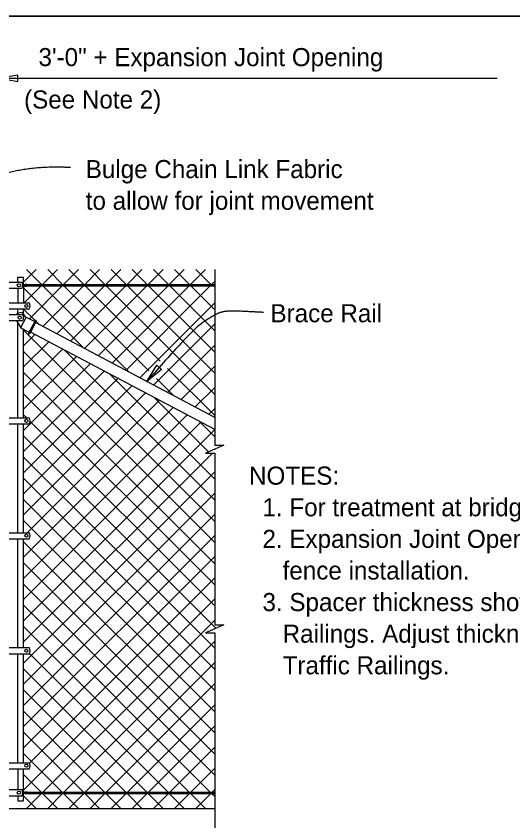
# Model space of a CAD drawing. Extents: x 0 to 41.2, y 0 to 26.
# Drawn here: x 28.76 to 34.3, y 17 to 25.96 of the extents above; entities that cross this region are included whole.
import ezdxf

# ---------------------------------------------------------------- set-up
doc = ezdxf.new("R2010")
doc.units = 0
for name, color, linetype in [('ActivePts-ConstElements', 7, 'Continuous'), ('Dimension', 7, 'Continuous'), ('Miscellaneous', 7, 'Continuous'), ('Miscellaneous1', 7, 'Continuous'), ('SteelMisc', 7, 'Continuous'), ('SupstrConc', 7, 'Continuous'), ('TextStructures', 7, 'Continuous')]:
    doc.layers.add(name, color=color, linetype=linetype)

msp = doc.modelspace()

# ---------------------------------------------------------------- linework, layer by layer
at = {"layer": 'ActivePts-ConstElements'}
msp.add_lwpolyline([(0, 0), (41.2106, 0), (41.2106, 25.96), (0, 25.96)], close=True, dxfattribs=at)
at = {"layer": 'Dimension'}
msp.add_line((25.6609, 25.2672), (34.1233, 25.2672), dxfattribs=at)
for points in [[(28.5762, 25.2672), (28.7845, 25.2319), (28.7845, 25.3025)], [(30.3825, 22.0243), (30.2184, 21.8914), (30.3296, 22.071)]]:
    msp.add_lwpolyline(points, close=True, dxfattribs=at)
for points in [[(30.9762, 23.1382), (30.9762, 21.1819), (31.0795, 21.1819), (30.9762, 21.1369), (30.8729, 21.0919), (30.9762, 21.0919), (30.9762, 20.1983)], [(30.9762, 20.1983), (30.9762, 19.1806), (31.0795, 19.1806), (30.9762, 19.1356), (30.8729, 19.0906), (30.9762, 19.0906), (30.9762, 17.1361)], [(30.9761, 17.1361), (30.9761, 15.7022), (31.0795, 15.7022), (30.9761, 15.6572), (30.8728, 15.6122), (30.9761, 15.6122), (30.9761, 13.3448)]]:
    msp.add_lwpolyline(points, dxfattribs=at)
for points in [[(29.3712, 24.2725), (28.9427, 24.2977), (28.2117, 24.0791), (27.9092, 23.4903), (27.7412, 21.9834)], [(31.5199, 22.6596), (31.3633, 22.6678), (31.0749, 22.6809), (30.9256, 22.6043), (30.718, 22.4586), (30.2184, 21.8914)]]:
    msp.add_open_spline(points, degree=2, dxfattribs=at)
at = {"layer": 'Miscellaneous'}
for p, q in [((28.8471, 22.996), (28.9872, 23.1361)), ((28.8798, 23.1361), (29.0465, 22.9695)), ((29.0563, 22.9695), (29.2229, 23.1361)), ((29.1155, 23.1361), (29.2822, 22.9695)), ((29.292, 22.9695), (29.4586, 23.1361)), ((29.3512, 23.1361), (29.5179, 22.9695)), ((29.5277, 22.9695), (29.6943, 23.1361)), ((29.5869, 23.1361), (29.7536, 22.9695)), ((29.7634, 22.9695), (29.9301, 23.1361)), ((29.8226, 23.1361), (29.9893, 22.9695)), ((29.9991, 22.9695), (30.1658, 23.1361)), ((30.0583, 23.1361), (30.225, 22.9695)), ((30.2348, 22.9695), (30.4015, 23.1361)), ((30.294, 23.1361), (30.4607, 22.9695)), ((30.4705, 22.9695), (30.6372, 23.1361)), ((30.5297, 23.1361), (30.6964, 22.9695)), ((30.7062, 22.9695), (30.8729, 23.1361)), ((30.7654, 23.1361), (30.9321, 22.9695)), ((28.8522, 22.7654), (29.0415, 22.9547)), ((28.912, 22.5894), (29.2772, 22.9547)), ((29.0612, 22.9547), (30.0194, 21.9966)), ((29.0612, 22.5029), (29.5129, 22.9547)), ((29.2154, 22.4214), (29.7486, 22.9547)), ((29.2969, 22.9547), (30.2432, 22.0084)), ((29.3696, 22.3399), (29.9843, 22.9547)), ((29.5238, 22.2584), (30.22, 22.9547)), ((29.5326, 22.9547), (30.3688, 22.1185)), ((29.678, 22.177), (30.4557, 22.9547)), ((29.7683, 22.9547), (30.9762, 21.7468)), ((29.8322, 22.0955), (30.6914, 22.9547)), ((29.9864, 22.014), (30.9271, 22.9547)), ((30.004, 22.9547), (30.9762, 21.9825)), ((30.2397, 22.9547), (30.9762, 22.2182)), ((30.4754, 22.9547), (30.9762, 22.4539)), ((30.7111, 22.9547), (30.9762, 22.6896)), ((30.9419, 22.9695), (30.9762, 23.0038)), ((28.8471, 22.9331), (29.5195, 22.2607)), ((28.8471, 22.6974), (28.9759, 22.5686)), ((30.1406, 21.9325), (30.9762, 22.768)), ((28.9859, 22.5586), (29.0197, 22.5249)), ((30.2948, 21.851), (30.9762, 22.5323)), ((28.8471, 22.4617), (30.9762, 20.3326)), ((28.8471, 22.2889), (28.9724, 22.4142)), ((28.8471, 22.0532), (29.1266, 22.3327)), ((28.8471, 21.8175), (29.2808, 22.2512)), ((29.3074, 22.2372), (30.9762, 20.5683)), ((30.449, 21.7695), (30.9762, 22.2966)), ((28.8471, 22.226), (30.9762, 20.0969)), ((28.8471, 21.5818), (29.435, 22.1697)), ((28.8471, 21.3461), (29.5892, 22.0882)), ((30.6032, 21.688), (30.9762, 22.0609)), ((28.8471, 21.1104), (29.7434, 22.0067)), ((28.8471, 21.9903), (30.9762, 19.8612)), ((29.8072, 21.973), (30.9762, 20.804)), ((30.4517, 22.0356), (30.9762, 21.5111)), ((28.8471, 20.8747), (29.8977, 21.9252)), ((30.3281, 21.9235), (30.5192, 21.7324)), ((28.8471, 20.639), (30.0519, 21.8437)), ((30.7575, 21.6065), (30.9762, 21.8252)), ((28.8471, 20.4033), (30.2061, 21.7622)), ((28.8471, 21.7546), (30.9762, 19.6255)), ((30.307, 21.7089), (30.9085, 21.1074)), ((28.8897, 20.2102), (30.3603, 21.6807)), ((28.8471, 19.9319), (30.5145, 21.5993)), ((28.8471, 21.5189), (28.8812, 21.4848)), ((28.8471, 19.6962), (30.6687, 21.5178)), ((30.9117, 21.525), (30.9762, 21.5895)), ((28.8471, 19.4605), (30.8229, 21.4363)), ((28.9195, 21.4465), (30.9762, 19.3898)), ((30.8069, 21.4448), (30.9762, 21.2754)), ((28.8471, 19.2248), (30.9762, 21.3538)), ((28.8471, 21.2832), (30.9891, 19.1412)), ((28.8471, 18.9891), (30.95, 21.0919)), ((28.8471, 21.0475), (30.9762, 18.9184)), ((28.8471, 18.7534), (30.9762, 20.8824)), ((28.8471, 20.8118), (30.9762, 18.6827)), ((28.8471, 18.5177), (30.9762, 20.6467)), ((28.8471, 20.5761), (30.9762, 18.447)), ((28.8471, 18.282), (30.9762, 20.411)), ((28.8471, 20.3404), (30.9762, 18.2113)), ((28.8471, 18.0462), (30.9762, 20.1753)), ((28.8471, 20.1047), (30.9762, 17.9756)), ((28.8471, 17.8105), (30.9762, 19.9396)), ((28.8471, 19.869), (30.9762, 17.7399)), ((28.8471, 19.6333), (30.9762, 17.5042)), ((28.9129, 17.6406), (30.9762, 19.7039)), ((28.8471, 17.3391), (30.9762, 19.4682)), ((28.8471, 19.3976), (30.9271, 17.3175)), ((29.0612, 17.3175), (30.9762, 19.2325)), ((28.8471, 19.1619), (30.6914, 17.3175)), ((29.2969, 17.3175), (30.9762, 18.9968)), ((28.9129, 18.8604), (30.4557, 17.3175)), ((29.5326, 17.3175), (30.9762, 18.7611)), ((28.8471, 18.6905), (30.22, 17.3175)), ((29.7683, 17.3175), (30.9762, 18.5254)), ((28.8471, 18.4548), (29.9843, 17.3175)), ((30.004, 17.3175), (30.9762, 18.2897)), ((28.8471, 18.219), (29.7486, 17.3175)), ((30.2397, 17.3175), (30.9762, 18.054)), ((28.8471, 17.9833), (29.5129, 17.3175)), ((30.4754, 17.3175), (30.9762, 17.8183)), ((28.8471, 17.7476), (29.2772, 17.3175)), ((30.7111, 17.3175), (30.9762, 17.5826)), ((28.8471, 17.5119), (29.0415, 17.3175)), ((28.8798, 17.1361), (29.0465, 17.3028)), ((29.0563, 17.3028), (29.2229, 17.1361)), ((29.1155, 17.1361), (29.2822, 17.3028)), ((29.292, 17.3028), (29.4586, 17.1361)), ((29.3512, 17.1361), (29.5179, 17.3028)), ((29.5277, 17.3028), (29.6943, 17.1361)), ((29.5869, 17.1361), (29.7536, 17.3028)), ((29.7634, 17.3028), (29.9301, 17.1361)), ((29.8226, 17.1361), (29.9893, 17.3028)), ((29.9991, 17.3028), (30.1658, 17.1361)), ((30.0583, 17.1361), (30.225, 17.3028)), ((30.2348, 17.3028), (30.4015, 17.1361)), ((30.294, 17.1361), (30.4607, 17.3028)), ((30.4705, 17.3028), (30.6372, 17.1361)), ((30.5297, 17.1361), (30.6964, 17.3028)), ((30.7062, 17.3028), (30.8729, 17.1361)), ((30.7654, 17.1361), (30.9321, 17.3028)), ((30.9419, 17.3028), (30.9762, 17.2685)), ((30.9468, 17.3175), (30.9762, 17.3469)), ((28.8471, 17.2762), (28.9872, 17.1361))]:
    msp.add_line(p, q, dxfattribs=at)
at = {"layer": 'Miscellaneous1'}
msp.add_lwpolyline([(0, 25.96), (41.2106, 25.96), (41.2106, 0), (0, 0)], close=True, dxfattribs=at)
at = {"layer": 'SteelMisc'}
for p, q in [((28.7846, 22.9966), (28.7846, 23.0528)), ((28.7846, 23.0528), (28.8471, 23.0528)), ((28.7846, 22.9966), (28.7846, 23.0528)), ((28.7846, 23.0528), (28.8471, 23.0528)), ((28.8471, 22.9726), (28.8471, 23.0528)), ((28.8471, 22.9726), (28.8471, 23.0528)), ((28.4206, 22.9966), (28.8303, 22.9966)), ((28.8376, 22.9741), (28.8668, 22.9695)), ((28.8377, 22.9741), (28.8669, 22.9695)), ((28.8381, 22.9537), (28.8717, 22.9593)), ((28.8382, 22.9691), (28.8642, 22.965)), ((28.8382, 22.9537), (28.8718, 22.9593)), ((28.8383, 22.9691), (28.8643, 22.965)), ((28.8385, 22.9585), (28.8684, 22.9634)), ((28.8386, 22.9585), (28.8685, 22.9634)), ((28.8471, 22.9676), (28.8471, 22.9598)), ((28.8471, 22.9676), (28.8471, 22.9598)), ((28.8471, 22.9552), (28.8471, 22.7653)), ((28.8471, 22.9552), (28.8471, 22.7653)), ((28.8842, 22.9547), (30.9762, 22.9547)), ((28.8855, 22.9695), (30.9762, 22.9695)), ((28.4206, 22.9289), (28.8299, 22.9289)), ((28.7846, 22.9288), (28.7846, 22.7653)), ((28.7846, 22.9288), (28.7846, 22.7653)), ((28.4206, 22.7654), (28.9116, 22.7654)), ((28.4206, 22.6977), (28.9109, 22.6977)), ((28.7846, 22.6487), (28.7846, 22.6977)), ((28.8471, 22.6411), (28.8471, 22.6977)), ((28.3139, 22.6358), (28.8387, 22.6358)), ((28.8763, 22.6083), (28.8126, 22.4877)), ((28.8728, 22.6018), (28.8381, 22.6549)), ((28.8763, 22.6083), (28.9706, 22.5585)), ((28.3139, 22.568), (28.8387, 22.568)), ((28.8168, 22.4958), (28.7699, 22.5675)), ((28.7846, 21.4848), (28.7846, 22.545)), ((28.9752, 22.5671), (28.9027, 22.43)), ((28.987, 22.5609), (28.9146, 22.4237)), ((30.9762, 21.4909), (28.9793, 22.5462)), ((28.9069, 22.4379), (28.8126, 22.4877)), ((28.8471, 21.4848), (28.8471, 22.4695)), ((30.9762, 21.3553), (28.9232, 22.4401)), ((28.4206, 21.4848), (28.9116, 21.4848)), ((28.4206, 21.4172), (28.9109, 21.4172)), ((28.7846, 20.2043), (28.7846, 21.4172)), ((28.8471, 20.2043), (28.8471, 21.4172)), ((28.4206, 20.2043), (28.9116, 20.2043)), ((28.4206, 20.1367), (28.9109, 20.1367)), ((28.7846, 18.9238), (28.7846, 20.1367)), ((28.8471, 18.9238), (28.8471, 20.1367)), ((28.9116, 18.9238), (28.2417, 18.9238)), ((28.4206, 18.8563), (28.9109, 18.8563)), ((28.7846, 17.6433), (28.7846, 18.8561)), ((28.8471, 17.6433), (28.8471, 18.8561)), ((28.4206, 17.6434), (28.9116, 17.6434)), ((28.4206, 17.5757), (28.9109, 17.5757)), ((28.7846, 17.5757), (28.7846, 17.3447)), ((28.8471, 17.3207), (28.8471, 17.5757)), ((28.3224, 17.3447), (28.8303, 17.3447)), ((28.3224, 17.3447), (28.8303, 17.3447)), ((28.8376, 17.3222), (28.8668, 17.3176)), ((28.8376, 17.3222), (28.8668, 17.3176)), ((28.8377, 17.3222), (28.8669, 17.3176)), ((28.8377, 17.3222), (28.8669, 17.3176)), ((28.8381, 17.3018), (28.8717, 17.3074)), ((28.8381, 17.3018), (28.8717, 17.3074)), ((28.8382, 17.3171), (28.8642, 17.3131)), ((28.8382, 17.3171), (28.8642, 17.3131)), ((28.8382, 17.3018), (28.8718, 17.3074)), ((28.8382, 17.3018), (28.8718, 17.3074)), ((28.8383, 17.3171), (28.8643, 17.3131)), ((28.8383, 17.3171), (28.8643, 17.3131)), ((28.8385, 17.3065), (28.8684, 17.3115)), ((28.8385, 17.3065), (28.8684, 17.3115)), ((28.8386, 17.3065), (28.8685, 17.3115)), ((28.8386, 17.3065), (28.8685, 17.3115)), ((28.8471, 17.3079), (28.8471, 17.3157)), ((28.8471, 17.3079), (28.8471, 17.3157)), ((28.8471, 17.3079), (28.8471, 17.3157)), ((28.8471, 17.3079), (28.8471, 17.3157)), ((28.8471, 17.2195), (28.8471, 17.3032)), ((28.8842, 17.3028), (30.9762, 17.3028)), ((28.8855, 17.3175), (30.9762, 17.3175)), ((28.3227, 17.2769), (28.8299, 17.2769)), ((28.3227, 17.2769), (28.8299, 17.2769)), ((28.7846, 17.2769), (28.7846, 17.2195)), ((28.7846, 17.2195), (28.8471, 17.2195))]:
    msp.add_line(p, q, dxfattribs=at)
for centre, start, end in [((28.981, 22.5639), 332.14902, 152.14902), ((28.9085, 22.4267), 152.14902, 332.14902)]:
    msp.add_arc(centre, 0.00673, start, end, dxfattribs=at)
for centre, major_axis in [((28.7943, 22.9621), (-0.0178, 0)), ((28.7943, 22.9621), (-0.0178, 0)), ((28.8779, 22.7326), (-0.0177, 0)), ((28.8779, 22.7326), (-0.0177, 0)), ((28.8028, 22.6012), (-0.0178, 0)), ((28.8779, 21.4521), (-0.0177, 0)), ((28.8779, 21.4521), (-0.0177, 0)), ((28.8779, 20.1716), (-0.0177, 0)), ((28.8779, 20.1716), (-0.0177, 0)), ((28.8779, 18.891), (-0.0177, 0)), ((28.8779, 18.891), (-0.0177, 0)), ((28.8779, 17.6106), (-0.0177, 0)), ((28.7943, 17.3102), (-0.0178, 0)), ((28.7943, 17.3102), (-0.0178, 0)), ((28.7943, 17.3102), (-0.0178, 0)), ((28.7943, 17.3102), (-0.0178, 0))]:
    msp.add_ellipse(centre, major_axis=major_axis, ratio=0.957868, dxfattribs=at)
for centre, major_axis, ratio, start_param, end_param in [((28.7609, 22.963), (0.0776, 0), 0.957868, 5.803915, 6.752041), ((28.7609, 22.963), (0.0776, 0), 0.957868, 5.803915, 6.752041), ((28.8694, 22.9596), (-0.0095, 0), 0.957868, 5.673972, 6.052579), ((28.8694, 22.9596), (-0.0095, 0), 0.957868, 5.673972, 6.052579), ((28.8694, 22.9596), (-0.0095, 0), 0.957868, 0.252467, 1.271421), ((28.8694, 22.9596), (-0.0095, 0), 0.957868, 0.252467, 1.271421), ((28.8635, 22.9555), (0.00982, 0), 0.957868, 0.655696, 1.505671), ((28.8635, 22.9555), (0.00982, 0), 0.957868, 0.655696, 1.505671), ((28.8654, 22.9604), (0.0115, -0.0041), 0.737732, 5.08821, 8.212701), ((28.8654, 22.9604), (0.0115, -0.0041), 0.737732, 5.08821, 8.212701), ((28.8688, 22.9579), (0.00301, 0), 0.957868, 3.28349, 5.170635), ((28.8688, 22.9579), (0.00301, 0), 0.957868, 3.28349, 5.170635), ((28.8695, 22.9601), (-0.00453, 0), 0.957868, 5.149727, 5.551998), ((28.8695, 22.9601), (-0.00453, 0), 0.957868, 5.149727, 5.551998), ((28.8667, 22.9588), (0.00527, 0), 0.957868, 5.058829, 7.342751), ((28.8667, 22.9588), (0.00527, 0), 0.957868, 5.058829, 7.342751), ((28.8711, 22.9612), (-0.00872, 0), 0.957868, 2.1008, 4.992926), ((28.8711, 22.9612), (-0.00872, 0), 0.957868, 2.1008, 4.992926), ((28.8688, 22.9579), (0.00301, 0), 0.957868, 0.004594, 0.141897), ((28.8688, 22.9579), (0.00301, 0), 0.957868, 0.004594, 0.141897), ((28.8772, 22.9608), (0.00944, 0), 0.957868, 4.316497, 6.557353), ((28.8772, 22.9608), (0.00944, 0), 0.957868, 4.316497, 6.557353), ((28.8776, 22.9617), (-0.00872, 0), 0.957868, 3.323334, 4.992926), ((28.8776, 22.9617), (-0.00872, 0), 0.957868, 3.323334, 4.992926), ((28.8776, 22.9617), (-0.00503, 0), 0.92697, 1.780895, 4.712389), ((28.8776, 22.9617), (-0.00503, 0), 0.92697, 1.780895, 4.712389), ((28.8824, 22.9562), (-0.0142, 0), 0.957868, 3.141593, 4.79635), ((28.8824, 22.9562), (-0.0142, 0), 0.957868, 3.141593, 4.79635), ((28.8744, 22.9412), (0.0274, 0), 0.957868, 0.628521, 1.149654), ((28.8744, 22.9412), (0.0274, 0), 0.957868, 0.628521, 1.149654), ((28.842, 22.7322), (0.0776, 0), 0.957868, 5.801244, 6.745158), ((28.842, 22.7322), (0.0776, 0), 0.957868, 5.801244, 6.745158), ((28.8215, 22.5866), (-0.0647, 0.0342), 0.957868, 4.95193, 6.011789), ((28.7695, 22.6016), (0.0776, 0), 0.957868, 5.810211, 6.75616), ((28.842, 21.4517), (0.0776, 0), 0.957868, 5.801046, 6.744962), ((28.842, 21.4517), (0.0776, 0), 0.957868, 5.801046, 6.744962), ((28.842, 20.1712), (0.0776, 0), 0.957868, 5.800848, 6.744767), ((28.842, 20.1712), (0.0776, 0), 0.957868, 5.800848, 6.744767), ((28.842, 18.8908), (0.0776, 0), 0.957868, 5.800848, 6.744767), ((28.842, 17.6101), (0.0776, 0), 0.957868, 5.800651, 6.745353), ((28.7609, 17.311), (0.0776, 0), 0.957868, 5.803915, 6.752041), ((28.7609, 17.311), (0.0776, 0), 0.957868, 5.803915, 6.752041), ((28.7609, 17.311), (0.0776, 0), 0.957868, 5.803915, 6.752041), ((28.7609, 17.311), (0.0776, 0), 0.957868, 5.803915, 6.752041), ((28.8694, 17.3077), (-0.0095, 0), 0.957868, 5.673972, 6.052579), ((28.8694, 17.3077), (-0.0095, 0), 0.957868, 5.673972, 6.052579), ((28.8694, 17.3077), (-0.0095, 0), 0.957868, 5.673972, 6.052579), ((28.8694, 17.3077), (-0.0095, 0), 0.957868, 5.673972, 6.052579), ((28.8694, 17.3077), (-0.0095, 0), 0.957868, 0.252467, 1.271421), ((28.8694, 17.3077), (-0.0095, 0), 0.957868, 0.252467, 1.271421), ((28.8694, 17.3077), (-0.0095, 0), 0.957868, 0.252467, 1.271421), ((28.8694, 17.3077), (-0.0095, 0), 0.957868, 0.252467, 1.271421), ((28.8635, 17.3035), (0.00982, 0), 0.957868, 0.655696, 1.505671), ((28.8635, 17.3035), (0.00982, 0), 0.957868, 0.655696, 1.505671), ((28.8635, 17.3035), (0.00982, 0), 0.957868, 0.655696, 1.505671), ((28.8635, 17.3035), (0.00982, 0), 0.957868, 0.655696, 1.505671), ((28.8654, 17.3084), (0.0115, -0.0041), 0.737732, 5.08821, 8.212701), ((28.8654, 17.3084), (0.0115, -0.0041), 0.737732, 5.08821, 8.212701), ((28.8654, 17.3084), (0.0115, -0.0041), 0.737732, 5.08821, 8.212701), ((28.8654, 17.3084), (0.0115, -0.0041), 0.737732, 5.08821, 8.212701), ((28.8688, 17.306), (0.00301, 0), 0.957868, 3.28349, 5.170635), ((28.8688, 17.306), (0.00301, 0), 0.957868, 3.28349, 5.170635), ((28.8688, 17.306), (0.00301, 0), 0.957868, 3.28349, 5.170635), ((28.8688, 17.306), (0.00301, 0), 0.957868, 3.28349, 5.170635), ((28.8695, 17.3082), (-0.00453, 0), 0.957868, 5.149727, 5.551998), ((28.8695, 17.3082), (-0.00453, 0), 0.957868, 5.149727, 5.551998), ((28.8695, 17.3082), (-0.00453, 0), 0.957868, 5.149727, 5.551998), ((28.8695, 17.3082), (-0.00453, 0), 0.957868, 5.149727, 5.551998), ((28.8667, 17.3069), (0.00527, 0), 0.957868, 5.058829, 7.342751), ((28.8667, 17.3069), (0.00527, 0), 0.957868, 5.058829, 7.342751), ((28.8667, 17.3069), (0.00527, 0), 0.957868, 5.058829, 7.342751), ((28.8667, 17.3069), (0.00527, 0), 0.957868, 5.058829, 7.342751), ((28.8711, 17.3093), (-0.00872, 0), 0.957868, 2.1008, 4.992926), ((28.8711, 17.3093), (-0.00872, 0), 0.957868, 2.1008, 4.992926), ((28.8711, 17.3093), (-0.00872, 0), 0.957868, 2.1008, 4.992926), ((28.8711, 17.3093), (-0.00872, 0), 0.957868, 2.1008, 4.992926), ((28.8688, 17.306), (0.00301, 0), 0.957868, 0.004594, 0.141897), ((28.8688, 17.306), (0.00301, 0), 0.957868, 0.004594, 0.141897), ((28.8688, 17.306), (0.00301, 0), 0.957868, 0.004594, 0.141897), ((28.8688, 17.306), (0.00301, 0), 0.957868, 0.004594, 0.141897), ((28.8772, 17.3089), (0.00944, 0), 0.957868, 4.316497, 6.557353), ((28.8772, 17.3089), (0.00944, 0), 0.957868, 4.316497, 6.557353), ((28.8772, 17.3089), (0.00944, 0), 0.957868, 4.316497, 6.557353), ((28.8772, 17.3089), (0.00944, 0), 0.957868, 4.316497, 6.557353), ((28.8776, 17.3098), (-0.00872, 0), 0.957868, 3.323334, 4.992926), ((28.8776, 17.3098), (-0.00872, 0), 0.957868, 3.323334, 4.992926), ((28.8776, 17.3098), (-0.00872, 0), 0.957868, 3.323334, 4.992926), ((28.8776, 17.3098), (-0.00872, 0), 0.957868, 3.323334, 4.992926), ((28.8776, 17.3098), (-0.00503, 0), 0.92697, 1.780895, 4.712389), ((28.8776, 17.3098), (-0.00503, 0), 0.92697, 1.780895, 4.712389), ((28.8776, 17.3098), (-0.00503, 0), 0.92697, 1.780895, 4.712389), ((28.8776, 17.3098), (-0.00503, 0), 0.92697, 1.780895, 4.712389), ((28.8824, 17.3043), (-0.0142, 0), 0.957868, 3.141593, 4.79635), ((28.8824, 17.3043), (-0.0142, 0), 0.957868, 3.141593, 4.79635), ((28.8824, 17.3043), (-0.0142, 0), 0.957868, 3.141593, 4.79635), ((28.8824, 17.3043), (-0.0142, 0), 0.957868, 3.141593, 4.79635), ((28.8744, 17.2893), (0.0274, 0), 0.957868, 0.628521, 1.149654), ((28.8744, 17.2893), (0.0274, 0), 0.957868, 0.628521, 1.149654), ((28.8744, 17.2893), (0.0274, 0), 0.957868, 0.628521, 1.149654), ((28.8744, 17.2893), (0.0274, 0), 0.957868, 0.628521, 1.149654)]:
    msp.add_ellipse(centre, major_axis=major_axis, ratio=ratio, start_param=start_param, end_param=end_param, dxfattribs=at)
at = {"layer": 'SupstrConc'}
msp.add_line((27.5763, 17.1361), (30.9761, 17.1361), dxfattribs=at)

# ---------------------------------------------------------------- texts
at = {"layer": 'Dimension'}
for s, p in [('Bulge Chain Link Fabric', (29.5393, 24.1553)), ('to allow for joint movement', (29.5393, 23.8033)), ('NOTES:', (31.3582, 20.7408)), ('  1. For treatment at bridge ends, see Sheet 1.', (31.3582, 20.3888)), ('  2. Expansion Joint Opening is the width at the time of', (31.3582, 20.0368)), ('     fence installation.', (31.3582, 19.6848)), ('  3. Spacer thickness shown is for Single-Slope Traffic', (31.3582, 19.3328)), ('     Railings. Adjust thickness as required for other', (31.3582, 18.9808)), ('     Traffic Railings.', (31.3582, 18.6288))]:
    msp.add_text(s, height=0.2016, dxfattribs=at).set_placement(p)
at = {"layer": 'TextStructures'}
for s, p in [('3\'-0" + Expansion Joint Opening', (29.0131, 25.4023)), ('(See Note 2)', (28.8524, 24.9306)), ('Brace Rail', (31.5972, 22.5497))]:
    msp.add_text(s, height=0.2016, dxfattribs=at).set_placement(p)

doc.saveas('drawing.dxf')
